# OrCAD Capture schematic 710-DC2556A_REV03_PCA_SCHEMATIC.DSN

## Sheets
1 PAGE2: size Custom; rev: 03; note: DEMO CIRTCUIT DC2556A
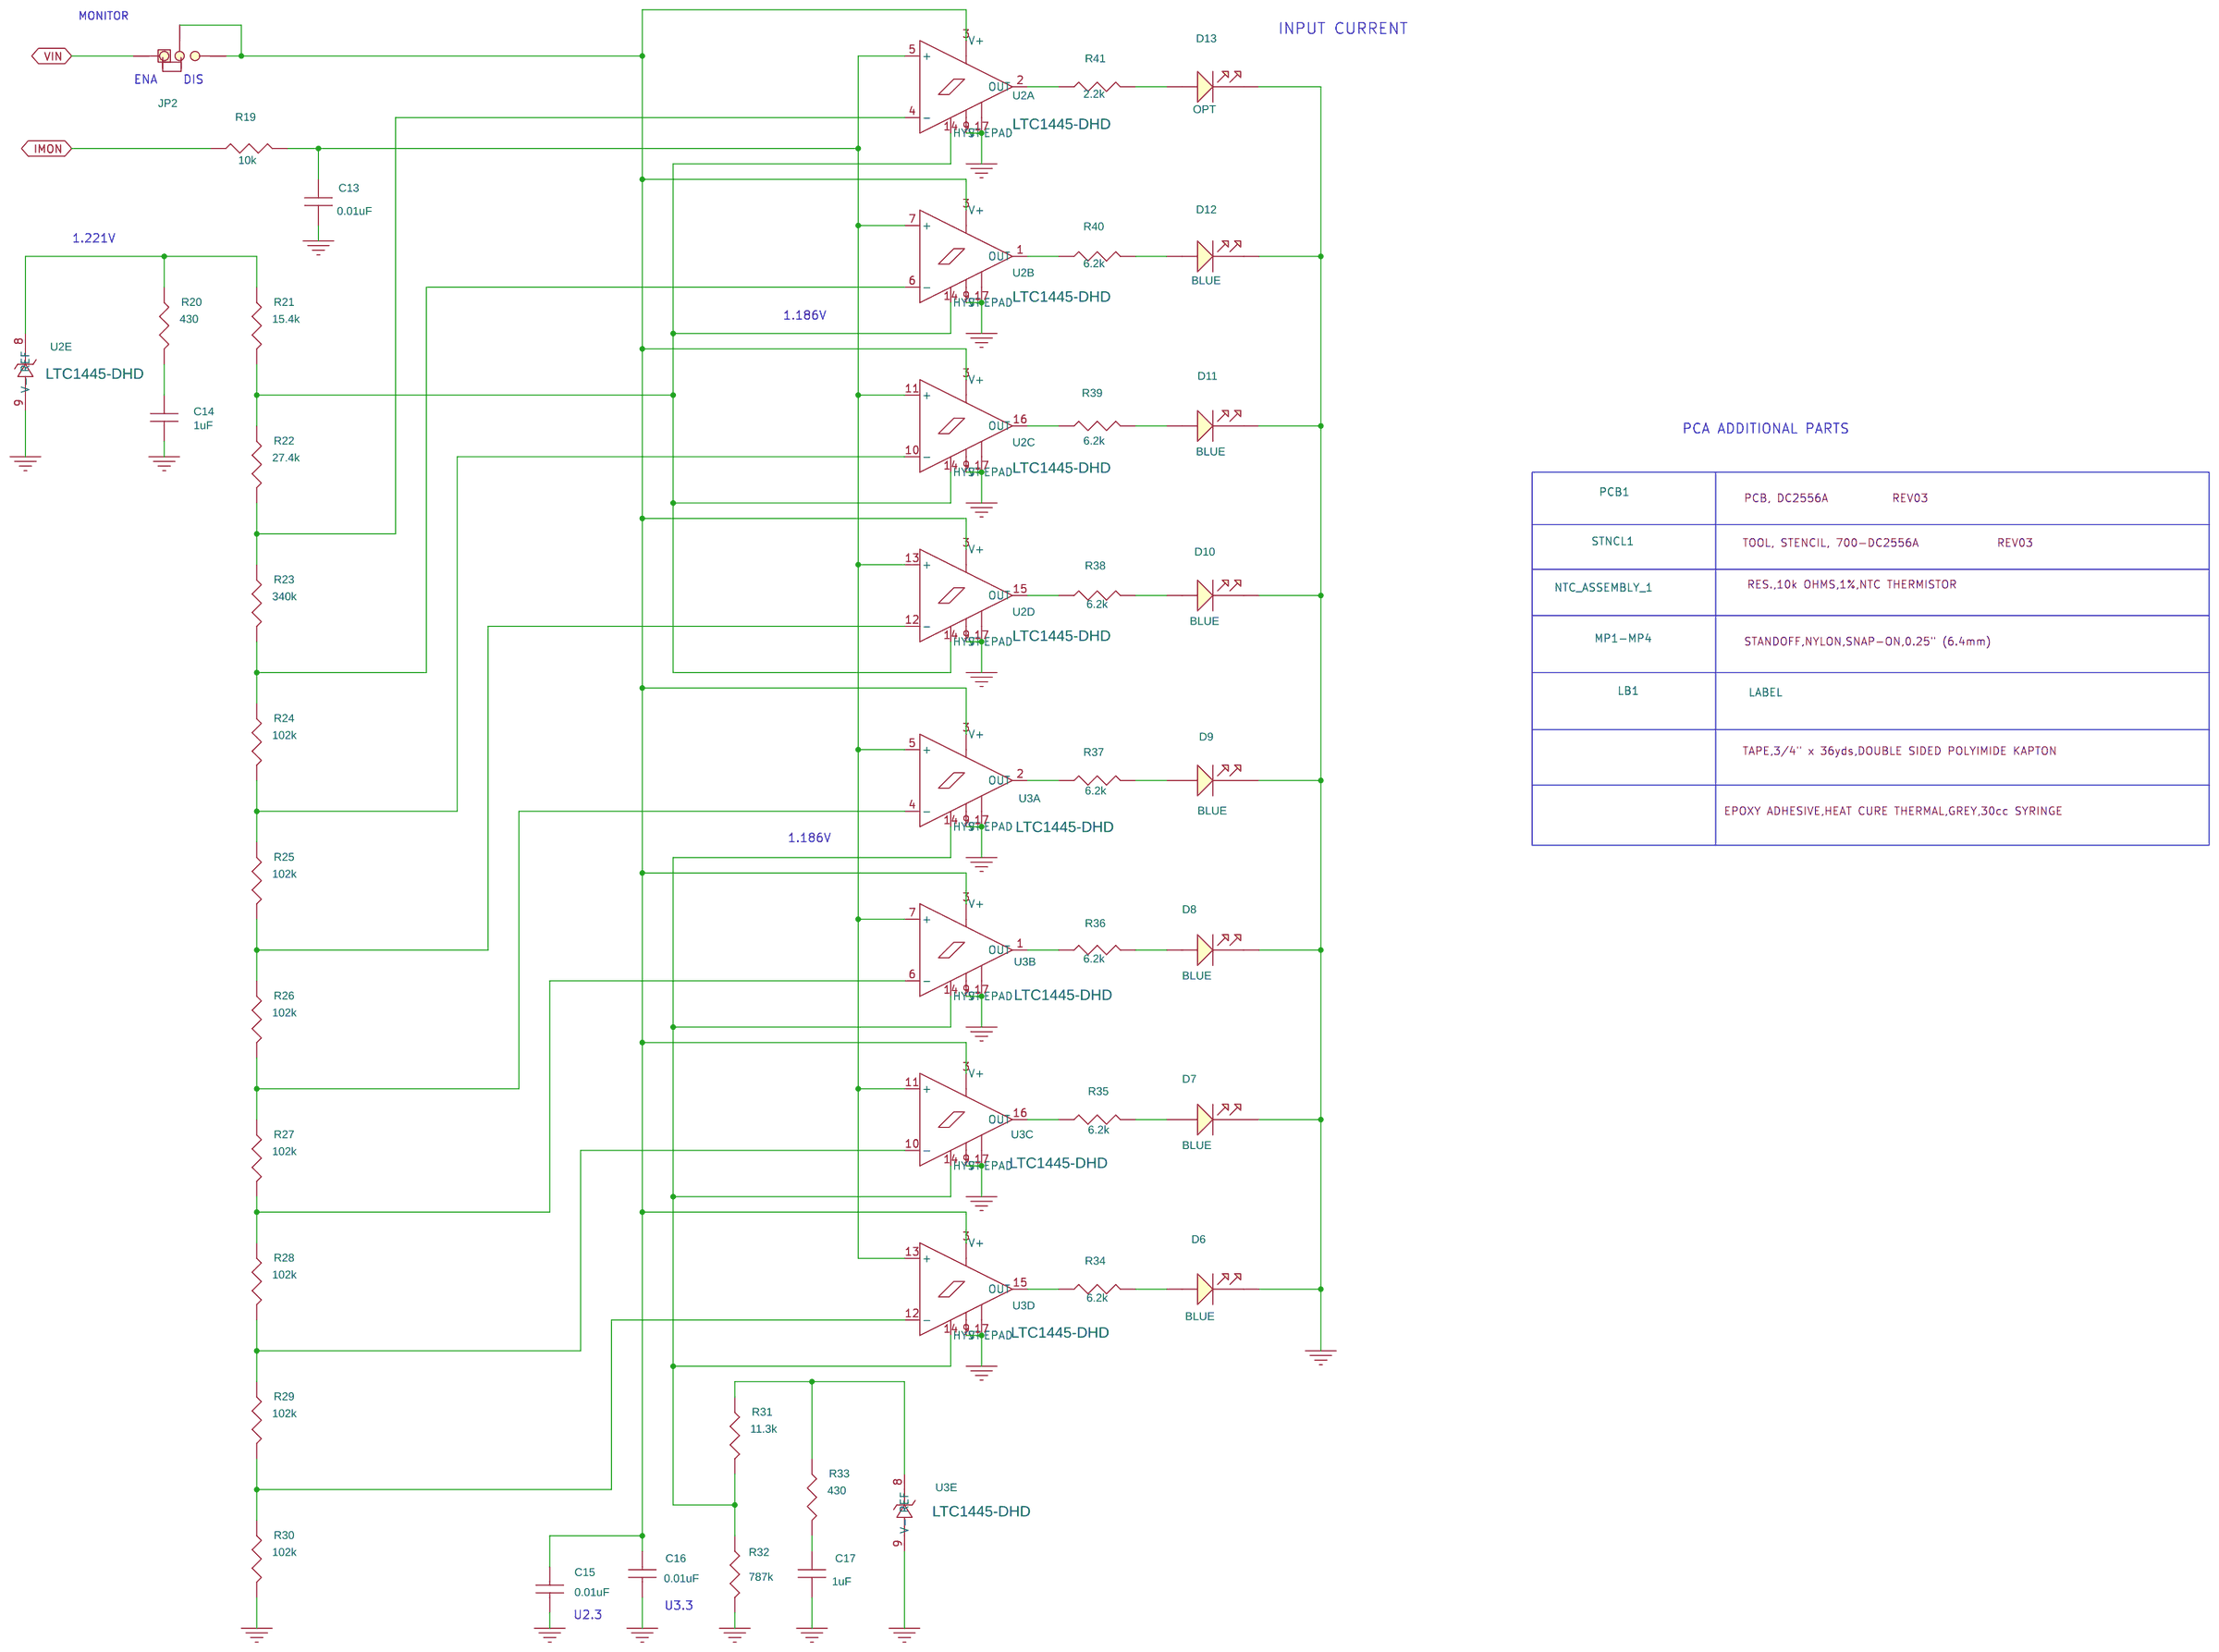
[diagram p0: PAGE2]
2 PAGE1: size A
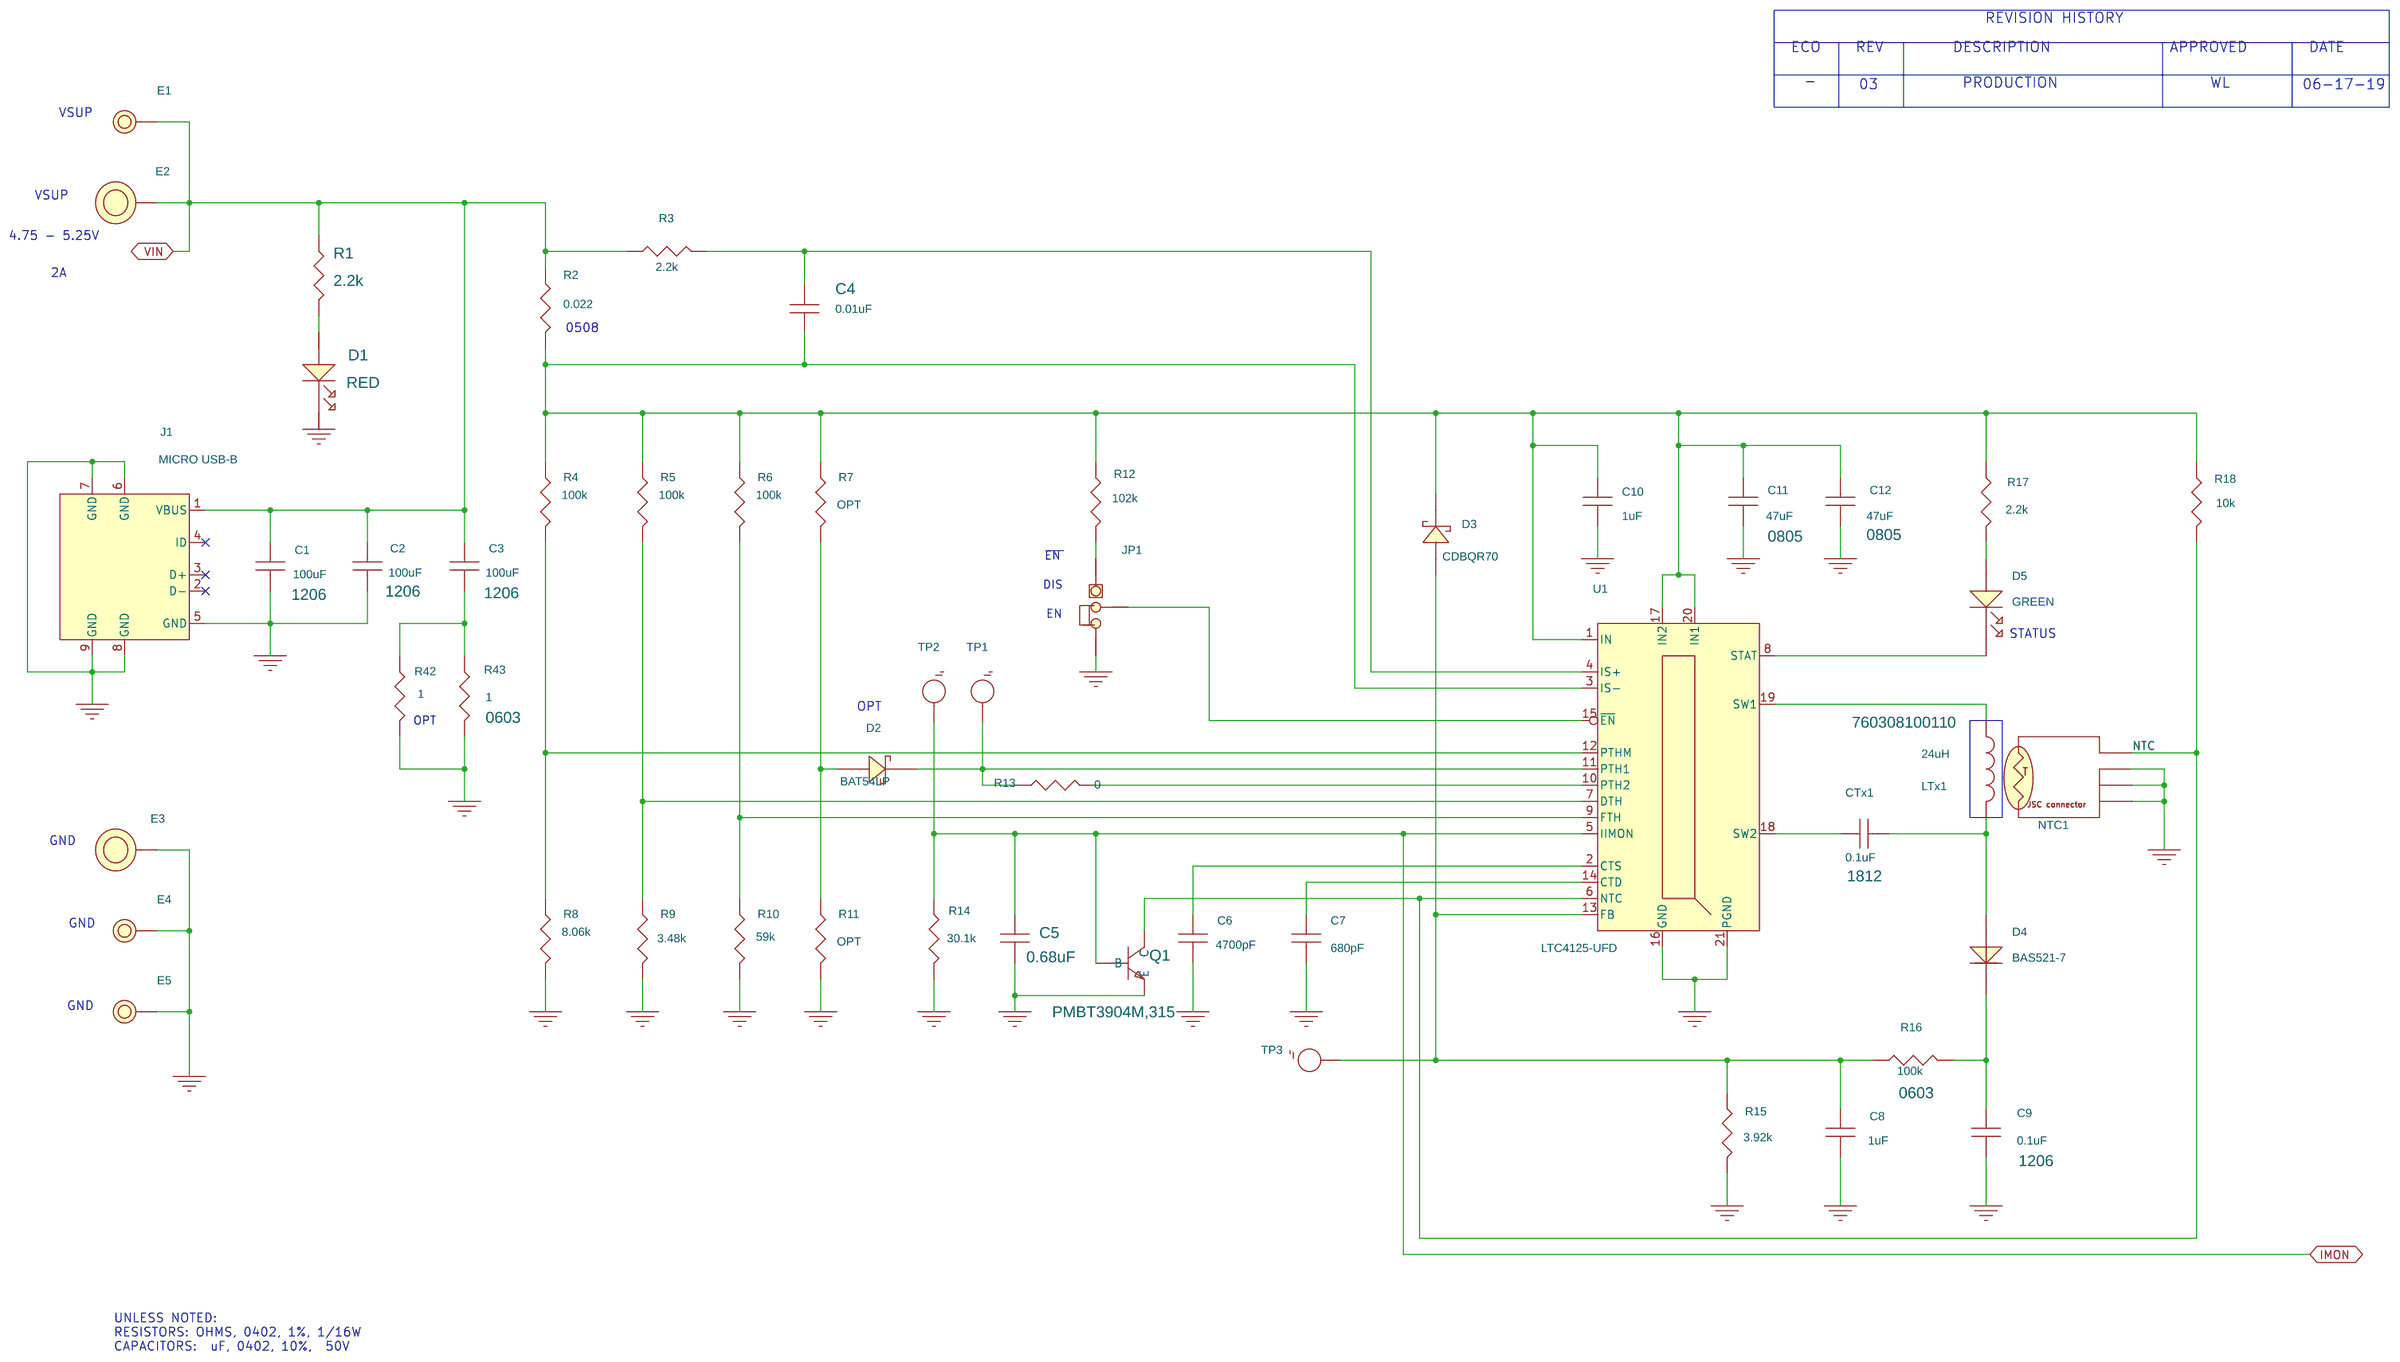
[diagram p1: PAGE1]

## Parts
sheet PAGE1
C1  100uF  [CC1206N]
C2  100uF  [CC1206N]
C3  100uF  [CC1206N]
C4  0.01uF  [CC0402M]
C5  0.68uF  [CC0402M]
C6  4700pF  [CC0402M]
C7  680pF  [CC0402M]
C8  1uF  [CC0402M]
C9  0.1uF  [CC1206N]
C10  1uF  [CC0402M]
C11  47uF  [CC0805N]
C12  47uF  [CC0805N]
CTx1  0.1uF  [CC1812M]
D1  RED  [LED_0603]
D2  BAT54LP  [DIODESINC-X1-DFN1006-2]
D3  CDBQR70  [SOD-923F-N]
D4  BAS521-7  [SOD-523N]
D5  GREEN  [LED_0603]
E1  TEST POINT  [MILLMAX2501]
E2  BANANA JACK  [KEY-575-4]
E3  BANANA JACK  [KEY-575-4]
E4  TEST POINT  [MILLMAX2501]
E5  TEST POINT  [MILLMAX2501]
J1  MICRO USB-B  [WURTH-629105136821]
JP1  HDR.  [HD1X3-079]
LTx1  24uH  [WURTH-760308100110]
NTC1  JSC COAXIAL SOCKET  [CONN-MM5829-2700]
Q1  PMBT3904M,315  [SOT883-3N]
R1  2.2k  [CR0402M]
R2  0.022  [SUSUMU-KRL2012]
R3  2.2k  [CR0402M]
R4  100k  [CR0402M]
R5  100k  [CR0402M]
R6  100k  [CR0402M]
R7  OPT  [CR0402M]
R8  8.06k  [CR0402M]
R9  3.48k  [CR0402M]
R10  59k  [CR0402M]
R11  OPT  [CR0402M]
R12  102k  [CR0402M]
R13  0  [CR0402M]
R14  30.1k  [CR0402M]
R15  3.92k  [CR0402M]
R16  100k  [CR0603N]
R17  2.2k  [CR0402M]
R18  10k  [CR0402M]
R42  1  [CR0603N]
R43  1  [CR0603N]
TP1  TEST PAD  [PADSTYLE7]
TP2  TEST PAD  [PADSTYLE7]
TP3  TEST PAD  [PADSTYLE7]
U1  LTC4125-UFD  [LTC-UFD-20-1711]
XJP1  SHUNT
sheet PAGE2
C13  0.01uF  [CC0402M]
C14  1uF  [CC0402M]
C15  0.01uF  [CC0402M]
C16  0.01uF  [CC0402M]
C17  1uF  [CC0402M]
D6  BLUE  [LED_0603]
D7  BLUE  [LED_0603]
D8  BLUE  [LED_0603]
D9  BLUE  [LED_0603]
D10  BLUE  [LED_0603]
D11  BLUE  [LED_0603]
D12  BLUE  [LED_0603]
D13  OPT  [LED_0603]
JP2  HDR.  [HD1X3-079]
LB1  LABEL  [895-0154_REV01]
MP1-MP4  STANDOFF  [MTG-8831]
MP5  TAPE  [UNASSIGNED]
MP6  EPOXY ADHESIVE  [UNASSIGNED]
NTC_ASSEMBLY_1  10k
PCB1  PCB, DC2556A
R19  10k  [CR0402M]
R20  430  [CR0402M]
R21  15.4k  [CR0402M]
R22  27.4k  [CR0402M]
R23  340k  [CR0402M]
R24  102k  [CR0402M]
R25  102k  [CR0402M]
R26  102k  [CR0402M]
R27  102k  [CR0402M]
R28  102k  [CR0402M]
R29  102k  [CR0402M]
R30  102k  [CR0402M]
R31  11.3k  [CR0402M]
R32  787k  [CR0402M]
R33  430  [CR0402M]
R34  6.2k  [CR0402M]
R35  6.2k  [CR0402M]
R36  6.2k  [CR0402M]
R37  6.2k  [CR0402M]
R38  6.2k  [CR0402M]
R39  6.2k  [CR0402M]
R40  6.2k  [CR0402M]
R41  2.2k  [CR0402M]
STNCL1  TOOL, STENCIL, 700-DC2556A
U2  LTC1445-DHD  [LTC-DHD-16-1707]  (sections A,B,C,D,E)
U3  LTC1445-DHD  [LTC-DHD-16-1707]  (sections A,B,C,D,E)
XJP3  SHUNT

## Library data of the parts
C1-C3 = CAP: CAP.,100uF,X5R,6.3V,10%,1206; CLASS: DISCRETE; Dielectric Type: X5R; FPLIST: CC1206N,CC1206L,CC1206M; Inventory Qty: 8002; Manufacturer: MURATA; Manufacturer PN: GRM31CR60J107KE39L; PART_NUMBER: 150-2327; Package Size: 1206; Rated Voltage: 6.3V; Tolerance: 10%
C4 C13 C15 C16 = CAP: CAP.,0.01uF,X7R,50V,10%,0402; CLASS: DISCRETE; Dielectric Type: X7R; FPLIST: CC0402N,CC0402L,CC0402M; Inventory Qty: 65996; Manufacturer: KEMET; Manufacturer PN: C0402C103K5RAC7867; PART_NUMBER: 150-0041; Package Size: 0402; Rated Voltage: 50V; Tolerance: 10%
C5 = CAP: CAP.,0.68uF,X5R,10V,10%,0402; CLASS: DISCRETE; Dielectric Type: X5R; FPLIST: CC0402N,CC0402L,CC0402M; Inventory Qty: 12568; Manufacturer: MURATA; Manufacturer PN: GRM155R61A684KE15D; PART_NUMBER: 150-3555; Package Size: 0402; Rated Voltage: 10V; Tolerance: 10%
C6 = CAP: CAP.,4700pF,X7R,50V,10%,0402; CLASS: DISCRETE; Dielectric Type: X7R; FPLIST: CC0402N,CC0402L,CC0402M; Inventory Qty: 14400; Manufacturer: AVX; Manufacturer PN: 04025C472KAT2A; PART_NUMBER: 150-0108; Package Size: 0402; Rated Voltage: 50V; Tolerance: 10%
C7 = CAP: CAP.,680pF,C0G,25V,5%,0402; CLASS: DISCRETE; Dielectric Type: C0G; FPLIST: CC0402N,CC0402L,CC0402M; Inventory Qty: 9188; Manufacturer: KEMET; Manufacturer PN: C0402C681J3GACTU; PART_NUMBER: 150-3563; Package Size: 0402; Package Type: Surface Mount, MLCC; Rated Voltage: 25V; Temperature Coefficient: C0G, NP0; Tolerance: 5%
C8 C10 C14 C17 = CAP: CAP.,1uF,X5R,16V,10%,0402; CLASS: DISCRETE; Dielectric Type: X5R; FPLIST: CC0402N,CC0402L,CC0402M; Inventory Qty: 40680; Manufacturer: AVX; Manufacturer PN: 0402YD105KAT2A; PART_NUMBER: 150-0250; Package Size: 0402; Rated Voltage: 16V; Tolerance: 10%
C9 = CAP: CAP.,0.1uF,X7R,250V,10%,1206; CLASS: DISCRETE; Dielectric Type: X7R; Inventory Qty: 4500; Manufacturer: KEMET; Manufacturer PN: C1206C104KARACTU; PART_NUMBER: 150-2489; Package Size: 1206; Package Type: Surface Mount, MLCC; Rated Voltage: 250V; Temperature Coefficient: X7R; Tolerance: 10%
C11 C12 = CAP: CAP.,47uF,X5R,6.3V,20%,0805; CLASS: DISCRETE; Dielectric Type: X5R; FPLIST: CC0805N,CC0805L,CC0805M; Inventory Qty: 29694; Manufacturer: MURATA; Manufacturer PN: GRM21BR60J476ME15L; PART_NUMBER: 150-0140; Package Size: 0805; Rated Voltage: 6.3V; Tolerance: 20%
CTx1 = CAP: CAP.,0.1uF,C0G,250V,5%,1812; CLASS: DISCRETE; Dielectric Type: C0G; Inventory Qty: 0; Manufacturer: TDK; Manufacturer PN: C4532C0G2E104J320KN; PART_NUMBER: 150-2490; Package Size: 1812; Package Type: Surface Mount, MLCC; Rated Voltage: 250V; Temperature Coefficient: C0G, NP0; Tolerance: 5%
D1 = LED_ALT: LED,RED,WATER-CLEAR,0603; CLASS: DISCRETE; FPLIST: LED_0603,LED-LTST-C193KRKT-5A; Inventory Qty: 16504; Manufacturer: LITE-ON; Manufacturer PN: LTST-C193KRKT-5A; PART_NUMBER: 270-0070; Package Size: 0603 (1608 Metric); Package Type: 0603
D2 = DIODE_SCHOTTKY_A_ALT: DIODE, SCHOTTKY, 30V 200MA, SOD-523; CLASS: DISCRETE; Manufacturer: DIODES INC.; Manufacturer PN: BAT54LP-7; PART_NUMBER: TMP-621; Package Size: SOD-523; Rated Voltage: 30V; Rated Voltage or Zener Voltage: 30V
D3 = DIODE_SCHOTTKY_A_ALT: DIODE,SCHOTTKY,70V,70mA,0402/SOD-923F; CLASS: DISCRETE; Inventory Qty: 1976; Manufacturer: COMCHIP; Max Forward Current or Rated Power: 70mA; PART_NUMBER: 210-0276; Package Size: 0402 (1005 Metric); Package Type: 0402/SOD-923F; Rated Voltage: 70V; Rated Voltage or Zener Voltage: 70V
D4 = DIODE_A_ALT: DIODE,SWITCHING,300V,250mA,SOD-523; CLASS: DISCRETE; FPLIST: SOD-523N,SOD-523L,SOD-523M; Inventory Qty: 7092; Manufacturer: DIODES INC.; Max Forward Current or Rated Power: 250mA; PART_NUMBER: 210-0122; Package Size: SC-79, SOD-523; Package Type: SOD-523; Rated Voltage: 300V; Rated Voltage or Zener Voltage: 300V
D5 = LED_ALT: LED,GREEN,MILKY WHITE DIFFUSED,0603; CLASS: DISCRETE; Inventory Qty: 9994; Manufacturer: LUMEX; Manufacturer PN: SML-LX0603SUGW-TR; PART_NUMBER: 270-0091; Package Size: 0603 (1608 Metric); Package Type: 0603
E1 E4 E5 = TESTPOINT_.219_MILL-MAX_2501: TEST POINT,TURRET,0.094" MTG. HOLE,PCB 0.062" THICK; CLASS: IO; Inventory Qty: 509910; Manufacturer: MILL-MAX; Manufacturer PN: 2501-2-00-80-00-00-07-0; PART_NUMBER: 260-0003
E2 E3 = BANANA_KEYSTONE-575-4: CONN.,BANANA JACK,FEMALE,THT,NON-INSULATED,SWAGE,0.218"; CLASS: IO; Inventory Qty: 209707; Manufacturer: KEYSTONE; Manufacturer PN: 575-4; PART_NUMBER: 250-0428
J1 = MICRO_USB_2.0_ALT1: CONN.,MICRO USB-B,RCPT., FEMALE,5-PIN,HORZ. R/A SMT; CLASS: IO; Inventory Qty: 2300; Manufacturer: WURTH ELEKTRONIK; Manufacturer PN: 629105136821; Operating Temperature Minimum: -40C - 105C; PART_NUMBER: 250-0714
JP1 JP2 = 1X3_C: CONN.,HDR.,MALE,1x3,2mm,THT, STR,NO SUBS. ALLOWED; CLASS: IO; Inventory Qty: 9734; Manufacturer: SAMTEC; Manufacturer PN: TMM-103-02-L-S; PART_NUMBER: 250-0638
LTx1 = IND_ALT: IND.,24uH,WIRELESS PWR CHRG TX COIL,10%,6A,0.1 OHM,ROUND 50mm DIA.; CLASS: DISCRETE; Inventory Qty: 517; Manufacturer: WURTH ELEKTRONIK; Manufacturer PN: 760308100110; PART_NUMBER: 200-0517; Package Size: ROUND 50mm DIA.; Tolerance: 10%
NTC1 = MM5829-2700RJ4: CONN.,JSC COAXIAL SOCKET,RCPT., FEMALE,SMD,1PORT, I/O TERM.; CLASS: IO; Inventory Qty: 3698; Manufacturer: MURATA; Manufacturer PN: MM5831-2700RB; PART_NUMBER: 250-0722
Q1 = NPN_C: XSTR.,NPN,40V,200mA,DFN1006-3 (SOT883),LEADLESS; CLASS: DISCRETE; Inventory Qty: 10988; Manufacturer: NEXPERIA; PART_NUMBER: 240-0292; Package Size: SC-101, SOT-883; Package Type: DFN1006-3 (SOT883); Polarity: NPN; Rated Power: 590mW; Rated Voltage: 40V
R1 R3 R17 R41 = RES: RES.,2.2k OHMS,5%,1/16W,0402,AEC-Q200; CLASS: DISCRETE; FPLIST: CR0402N,CR0402L,CR0402M; Inventory Qty: 62324; Manufacturer: VISHAY; Manufacturer PN: CRCW04022K20JNED; PART_NUMBER: 100-0324; Package Size: 0402; Rated Power: 1/16W; Temperature Coefficient: 200ppm; Tolerance: 5%
R2 = RES: RES.,0.022 OHM,1%,1W,0805, LONG-SIDE TERM.,AEC-Q200, SENSE; CLASS: DISCRETE; Inventory Qty: 0; Manufacturer: Susumu; Manufacturer PN: KRL2012E-M-R022-F-T5; PART_NUMBER: 100-0975; Package Size: 0805, LONG-SIDE TERM.; Rated Power: 1W; Temperature Coefficient: +/-50PPM; Tolerance: 1%
R4-R6 = RES: RES.,100k OHMS,1%,1/16W,0402,AEC-Q200; CLASS: DISCRETE; Inventory Qty: 136632; Manufacturer: VISHAY; Manufacturer PN: CRCW0402100KFKED; PART_NUMBER: 100-2396; Package Size: 0402; Rated Power: 1/16W; Temperature Coefficient: 100ppm; Tolerance: 1%
R7 R11 = RES: RES., OPTION, 0402; CLASS: DISCRETE; PART_NUMBER: 100-0357; Package Size: 0402
R8 = RES: RES.,8.06k OHMS,1%,1/16W,0402,AEC-Q200; CLASS: DISCRETE; FPLIST: CR0402N,CR0402L,CR0402M; Inventory Qty: 13375; Manufacturer: NIC; Manufacturer PN: NRC04F8061TRF; PART_NUMBER: 100-2983; Package Size: 0402; Rated Power: 1/16W; Temperature Coefficient: +/-100PPM; Tolerance: 1%
R9 = RES: RES.,3.48k OHMS,1%,1/16W,0402,AEC-Q200; CLASS: DISCRETE; FPLIST: CR0402N,CR0402L,CR0402M; Inventory Qty: 1989; Manufacturer: VISHAY; Manufacturer PN: CRCW04023K48FKED; PART_NUMBER: 100-2984; Package Size: 0402; Rated Power: 1/16W; Temperature Coefficient: +/-100PPM; Tolerance: 1%
R10 = RES: RES.,59k OHMS,1%,1/16W,0402,AEC-Q200; CLASS: DISCRETE; FPLIST: CR0402N,CR0402L,CR0402M; Inventory Qty: 34456; Manufacturer: NIC; Manufacturer PN: NRC04F5902TRF; PART_NUMBER: 100-0515; Package Size: 0402; Rated Power: 1/16W; Temperature Coefficient: 100ppm; Tolerance: 1%
R12 R24-R30 = RES: RES.,102k OHMS,1%,1/16W,0402,AEC-Q200; CLASS: DISCRETE; FPLIST: CR0402N,CR0402L,CR0402M; Inventory Qty: 26868; Manufacturer: STACKPOLE ELECTRONICS, INC.; Manufacturer PN: RMCF0402FT102K; PART_NUMBER: 100-2539; Package Size: 0402; Rated Power: 1/16W; Temperature Coefficient: 100ppm/C; Tolerance: 1%
R13 = RES: RES.,0 OHM,1/16W,0402; CLASS: DISCRETE; FPLIST: CR0402N,CR0402L,CR0402M; Inventory Qty: 222931; Manufacturer: ROHM; Manufacturer PN: MCR01MZPJ000; PART_NUMBER: 100-0215; Package Size: 0402; Rated Power: 1/16W
R14 = RES: RES.,30.1k OHMS,1%,1/16W,0402,AEC-Q200; CLASS: DISCRETE; FPLIST: CR0402N,CR0402L,CR0402M; Inventory Qty: 83476; Manufacturer: NIC; Manufacturer PN: NRC04F3012TRF; PART_NUMBER: 100-2935; Package Size: 0402; Rated Power: 1/16W; Temperature Coefficient: 100ppm; Tolerance: 1%
R15 = RES: RES.,3.92k OHMS,1%,1/10W,0402,AEC-Q200; CLASS: DISCRETE; FPLIST: CR0402N,CR0402L,CR0402M; Inventory Qty: 5900; Manufacturer: PANASONIC; Manufacturer PN: ERJ2RKF3921X; PART_NUMBER: 100-0732; Package Size: 0402; Rated Power: 1/10W; Temperature Coefficient: 100ppm; Tolerance: 1%
R16 = RES: RES.,100k OHMS,1%,1/10W,0603,350V, AEC-Q200; CLASS: DISCRETE; FPLIST: CR0603N,CR0603L,CR0603M; Inventory Qty: 13800; Manufacturer: ROHM; Manufacturer PN: KTR03EZPF1003; PART_NUMBER: 100-2986; Package Size: 0603; Rated Power: 1/10W; Temperature Coefficient: +/-100PPM; Tolerance: 1%
R18 = RES: RES.,10k OHMS,5%,1/16W,0402; CLASS: DISCRETE; Inventory Qty: 78912; Manufacturer: SAMSUNG; Manufacturer PN: RC1005J103CS; PART_NUMBER: 100-0023; Package Size: 0402; Rated Power: 1/16W; Temperature Coefficient: +/-100ppm; Tolerance: 5%
R42 R43 = RES: RES.,1 OHM,5%,1/10W,0603,AEC-Q200; CLASS: DISCRETE; FPLIST: CR0603N,CR0603L,CR0603M; Inventory Qty: 26822; Manufacturer: PANASONIC; Manufacturer PN: ERJ3GEYJ1R0V; PART_NUMBER: 100-0149; Package Size: 0603; Rated Power: 1/10W; Temperature Coefficient: -100ppm to +600pmm; Tolerance: 5%
TP1 TP3 = TESTPOINT_FILLED_CIRCLE: TESTPOINT, PCB COPPER FEATURE; CLASS: IO; Manufacturer: N/A; Manufacturer PN: N/A; PART_NUMBER: PCBPADS-1
TP2 = TESTPOINT_FILLED_CIRCLE: TESTPOINT, PCB COPPER FEATURE; CLASS: IO; FPLIST: PADSTYLE1,PADSTYLE2,PADSTYLE3,PADSTYLE4,PADSTYLE5,PADSTYLE6,PADSTYLE7,PADSTYLE8; Manufacturer: N/A; Manufacturer PN: N/A; PART_NUMBER: PCBPADS-1
U1 = LTC4125-UFD: IC,5W Wireless Power Transmitter,QFN-20 (4x5),AutoResonant; CLASS: IC; Inventory Qty: 36; Manufacturer: LINEAR TECH.; Manufacturer PN: LTC4125EUFD#PBF; PART_NUMBER: LTC4125EUFD#PBF; Package Size: 20-WFQFN Exposed Pad; Package Type: QFN-20 (4x5); Supply Voltage: 3 V - 5.5 V
XJP1 XJP3 = SHUNT_2MM_B: CONN.,SHUNT,FEMALE,2 POS,2mm; CLASS: IO; Inventory Qty: 63006; Manufacturer: Wurth Elektronik; Manufacturer PN: 60800213421; PART_NUMBER: 250-0485
D6-D12 = LED_ALT: LED,BLUE,WATER CLEAR,0603; CLASS: DISCRETE; Inventory Qty: 14900; Manufacturer: LUMEX; Manufacturer PN: SML-LXFP0603USBCTR; PART_NUMBER: 270-0119; Package Size: 0603 (1608 Metric); Package Type: 0603
D13 = LED_ALT: LED, OPTION, 0603; CLASS: DISCRETE; Manufacturer: Lumex Opto/Components Inc.; Manufacturer PN: SML-LX0603SIW-TR; PART_NUMBER: 270-0107; Package Size: 0603; Package Type: 0603 SMD
LB1 = BLANK_LABEL: LABEL SPEC, DEMO BOARD SERIAL NUMBER; Inventory Qty: 0; Manufacturer: BRADY; Manufacturer PN: THT-96-717-10; PART_NUMBER: 895-0154
MP1-MP4 = BLANK_MECHANICAL_PART: STANDOFF,NYLON,SNAP-ON,0.25" (6.4mm); CLASS: MECHANICAL PART; Inventory Qty: 189640; Manufacturer: KEYSTONE; Manufacturer PN: 8831; PART_NUMBER: 763-0006
MP5 = BLANK_MECHANICAL_PART: TAPE,3/4" x 36yds,DOUBLE SIDED POLYIMIDE KAPTON; CLASS: DISCRETE; Inventory Qty: 28304; Manufacturer: BERTECH; Manufacturer PN: PPTDE-3/4; PART_NUMBER: 450-0007
MP6 = BLANK_MECHANICAL_PART: EPOXY ADHESIVE,HEAT CURE THERMAL,GREY,30cc SYRINGE; CLASS: DISCRETE; Inventory Qty: 0; Manufacturer: DOW CORNING; Manufacturer PN: 3-6752; PART_NUMBER: 650-0005
NTC_ASSEMBLY_1 = BLANK_PINLESS_MECHANICAL_PART: RES.,10k OHMS,1%,NTC THERMISTOR; CLASS: DISCRETE; Inventory Qty: 1990; Manufacturer: MURATA; Manufacturer PN: FTN55XH103FD4B; PART_NUMBER: 100-0959; Tolerance: 1%
PCB1 = BLANK_PCB_PART: BOM Notes: REV03; CLASS: DISCRETE; Inventory Qty: 0; Manufacturer: PHASE 3; Manufacturer PN: 600-DC2556A; PART_NUMBER: 600-DC2556A
R19 = RES: RES.,10k OHMS,5%,1/16W,0402; CLASS: DISCRETE; FPLIST: CR0402N,CR0402L,CR0402M; Inventory Qty: 78912; Manufacturer: SAMSUNG; Manufacturer PN: RC1005J103CS; PART_NUMBER: 100-0023; Package Size: 0402; Rated Power: 1/16W; Temperature Coefficient: +/-100ppm; Tolerance: 5%
R20 R33 = RES: RES.,430 OHMS,5%,1/16W,0402; CLASS: DISCRETE; FPLIST: CR0402N,CR0402L,CR0402M; Inventory Qty: 39842; Manufacturer: SAMSUNG; Manufacturer PN: RC1005J431CS; PART_NUMBER: 100-0472; Package Size: 0402; Rated Power: 1/16W; Temperature Coefficient: +/-100PPM; Tolerance: 5%
R21 = RES: RES.,15.4k OHMS,1%,1/16W,0402,AEC-Q200; CLASS: DISCRETE; FPLIST: CR0402N,CR0402L,CR0402M; Inventory Qty: 23000; Manufacturer: KOA SPEER; Manufacturer PN: RK73H1ETTP1542F; PART_NUMBER: 100-2987; Package Size: 0402; Rated Power: 1/16W; Temperature Coefficient: +/-100PPM; Tolerance: 1%
R22 = RES: RES.,27.4k OHMS,1%,1/16W,0402,AEC-Q200; CLASS: DISCRETE; FPLIST: CR0402N,CR0402L,CR0402M; Inventory Qty: 45300; Manufacturer: NIC; Manufacturer PN: NRC04F2742TRF; PART_NUMBER: 100-0842; Package Size: 0402; Rated Power: 1/16W; Temperature Coefficient: 100ppm; Tolerance: 1%
R23 = RES: RES.,340k OHMS,1%,1/16W,0402; CLASS: DISCRETE; FPLIST: CR0402N,CR0402L,CR0402M; Inventory Qty: 5000; Manufacturer: YAGEO; Manufacturer PN: RC0402FR-07340KL; PART_NUMBER: 100-0466; Package Size: 0402; Rated Power: 1/16W; Temperature Coefficient: +/-100PPM; Tolerance: 1%
R31 = RES: RES.,11.3k OHMS,1%,1/16W,0402,AEC-Q200; CLASS: DISCRETE; FPLIST: CR0402N,CR0402L,CR0402M; Inventory Qty: 34000; Manufacturer: NIC; Manufacturer PN: NRC04F1132TRF; PART_NUMBER: 100-2989; Package Size: 0402; Rated Power: 1/16W; Temperature Coefficient: +/-100; Tolerance: 1%
R32 = RES: RES.,787k OHMS,1%,1/16W,0402,AEC-Q200; CLASS: DISCRETE; FPLIST: CR0402N,CR0402L,CR0402M; Inventory Qty: 33778; Manufacturer: NIC; Manufacturer PN: NRC04F7873TRF; PART_NUMBER: 100-0326; Package Size: 0402; Rated Power: 1/16W; Temperature Coefficient: 100ppm/C; Tolerance: 1%
R34-R40 = RES: RES.,6.2k OHMS,1%,1/16W,0402; CLASS: DISCRETE; FPLIST: CR0402N,CR0402L,CR0402M; Inventory Qty: 24832; Manufacturer: SAMSUNG; Manufacturer PN: RC1005F622CS; PART_NUMBER: 100-2990; Package Size: 0402; Rated Power: 1/16W; Temperature Coefficient: +/-100ppm; Tolerance: 1%
STNCL1 = BLANK_STENCIL_PART: BOM Notes: REV03; CLASS: DISCRETE; Inventory Qty: 0; Manufacturer: LINEAR TECH.; Manufacturer PN: 830-DC2556A; PART_NUMBER: 830-DC2556A
U2 U3 = LTC1443_44_45-DHD: IC,QUAD COMPARATOR LP 1.221VREF,DFN-16 (5x4); CLASS: IC; Inventory Qty: 36; Manufacturer: LINEAR TECH.; Manufacturer PN: LTC1445CDHD#PBF; PART_NUMBER: LTC1445CDHD#PBF; Package Size: 16-WFDFN Exposed Pad; Package Type: DFN-16 (5x4); Supply Voltage: 2V-11V, 1 V-5.5V

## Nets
GND: C1.2 C2.2 C5.2 C6.2 C7.2 C8.2 C9.2 C10.2 C11.2 C12.2 C13.2 C14.2 C15.2 C16.2 C17.2 D1.1(CATHODE) D6.1(CATHODE) D7.1(CATHODE) D8.1(CATHODE) D9.1(CATHODE) D10.1(CATHODE) D11.1(CATHODE) D12.1(CATHODE) D13.1(CATHODE) E3.1 E4.1 E5.1 J1.5(GND) J1.6(GND) J1.7(GND) J1.8(GND) J1.9(GND) JP1.3 NTC1.2(pin2) NTC1.3(pin3) NTC1.4(pin4) Q1.2(E) R8.2 R9.2 R10.2 R11.2 R14.2 R15.2 R30.2 R32.2 R42.2 R43.2 U1.16(GND) U1.21(PGND) U2.9(V-) U2.17(EPAD) U3.9(V-) U3.17(EPAD)
VIN: C1.1 C2.1 C3.1 E1.1 E2.1 J1.1(VBUS) JP2.1 R1.1 R2.2 R3.1
IMON: C5.1 Q1.1(B) R14.1 R19.1 TP2.1 U1.5(IIMON)
NTC: NTC1.1(pin1) Q1.3(C) R18.2 U1.6(NTC)
N17515052: CTx1.2 D4.2(A) LTx1.2
N17515313: LTx1.1 U1.19(SW1)
N17515474: D5.1(CATHODE) U1.8(STAT)
N17515801: C8.1 D3.2(A) R15.1 R16.1 TP3.1 U1.13(FB)
N17517002: C4.1 C10.1 C11.1 C12.1 D3.1(C) R2.1 R4.1 R5.1 R6.1 R7.1 R12.1 R17.1 R18.1 U1.1(IN) U1.3(IS-) U1.17(IN2) U1.20(IN1)
N17520315: R6.2 R10.1 U1.9(FTH)
N17520403: R5.2 R9.1 U1.7(DTH)
N17520528: R4.2 R8.1 U1.12(PTHM)
N17534793: C6.1 U1.2(CTS)
N17562170: CTx1.1 U1.18(SW2)
N17638271: C9.1 D4.1(C) R16.2
N17657674: D2.2(A) R7.2 R11.1
N17657986: D2.1(C) R13.1 TP1.1 U1.11(PTH1)
N17659451: R13.2 U1.10(PTH2)
N17669208: R41.1 U2.2(OUT)
N17669210: R37.1 U3.2(OUT)
N17669212: R38.1 U2.15(OUT)
N17669214: R40.1 U2.1(OUT)
N17669216: R39.1 U2.16(OUT)
N17669218: R36.1 U3.1(OUT)
N17669220: R34.1 U3.15(OUT)
N17669276: R28.2 R29.1 U3.10(-)
N17669282: R35.1 U3.16(OUT)
N17669297: R27.2 R28.1 U3.6(-)
N17669326: R21.2 R22.1 U2.14(HYST)
N17669328: C15.1 C16.1 JP2.2 JP2.3 U2.3(V+) U3.3(V+)
N17669353: R20.1 R21.1 U2.8(REF)
N17669363: C14.1 R20.2
N17669392: R31.2 R32.1 U3.14(HYST)
N17669460: C13.1 R19.2 U2.5(+) U2.7(+) U2.11(+) U2.13(+) U3.5(+) U3.7(+) U3.11(+) U3.13(+)
N17669492: R22.2 R23.1 U2.4(-)
N17669494: R23.2 R24.1 U2.6(-)
N17669496: R24.2 R25.1 U2.10(-)
N17669498: R25.2 R26.1 U2.12(-)
N17669500: R26.2 R27.1 U3.4(-)
N17669502: R29.2 R30.1 U3.12(-)
N17669713: R31.1 R33.1 U3.8(REF)
N17670009: D13.2(ANODE) R41.2
N17670013: D12.2(ANODE) R40.2
N17670017: D11.2(ANODE) R39.2
N17670019: D10.2(ANODE) R38.2
N17670023: D9.2(ANODE) R37.2
N17670025: D8.2(ANODE) R36.2
N17670027: D7.2(ANODE) R35.2
N17670029: D6.2(ANODE) R34.2
N17703086: C4.2 R3.2 U1.4(IS+)
N17718079: D5.2(ANODE) R17.2
N17724165: C7.1 U1.14(CTD)
N17725932: JP1.1 R12.2
N17726092: JP1.2 U1.15(~{EN})
N17737368: C3.2 R42.1 R43.1
N17825155: D1.2(ANODE) R1.2
N17827507: C17.1 R33.2

Not connected (* = marked no-connect by the designer): J1 2(D-)* 3(D+)* 4(ID)*

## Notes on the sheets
sheet 1
- MONITOR
- INPUT CURRENT
- ENA
- DIS
- 1.221V
- 1.186V
- PCA ADDITIONAL PARTS
- 1.186V
- U2.3
- U3.3
sheet 2
- REVISION HISTORY
- ECO
- REV
- DESCRIPTION
- APPROVED
- DATE
- -
- 03
- PRODUCTION
- WL
- 06-17-19
- VSUP
- VSUP
- 4.75 - 5.25V
- 2A
- 0508
- EN
- DIS
- EN
- STATUS
- OPT
- OPT
- GND
- GND
- GND
- UNLESS NOTED:
  RESISTORS: OHMS, 0402, 1%, 1/16W
  CAPACITORS:  uF, 0402, 10%,  50V
